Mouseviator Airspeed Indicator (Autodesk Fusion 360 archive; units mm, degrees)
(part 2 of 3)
sketch "Sketch3" plane through (0, 0, 13.75) normal (0, 0, 1) x axis (1, 0, 0)
  line L1 (0, 6.7839) -> (0, 0)
  arc A1 centre (0, 5.8437) radius 0.9477 clockwise from (-0.9442, 5.9252) to (0.9442, 5.9252)
  circle C1 centre (0, 0) radius 6
  arc A2 centre (-1.8058, 5.5576) radius 0.9477 clockwise from (-2.729, 5.3435) to (-0.933, 5.927)
  arc A3 centre (-3.4348, 4.7276) radius 0.9477 clockwise from (-4.2466, 4.2387) to (-2.7189, 5.3486)
  arc A4 centre (-4.7276, 3.4348) radius 0.9477 clockwise from (-5.3486, 2.7189) to (-4.2387, 4.2466)
  arc A5 centre (-5.5576, 1.8058) radius 0.9477 clockwise from (-5.927, 0.933) to (-5.3435, 2.729)
  arc A6 centre (-5.8437, 0) radius 0.9477 clockwise from (-5.9252, -0.9442) to (-5.9252, 0.9442)
  arc A7 centre (-5.5576, -1.8058) radius 0.9477 clockwise from (-5.3435, -2.729) to (-5.927, -0.933)
  arc A8 centre (-4.7276, -3.4348) radius 0.9477 clockwise from (-4.2387, -4.2466) to (-5.3486, -2.7189)
  arc A9 centre (-3.4348, -4.7276) radius 0.9477 clockwise from (-2.7189, -5.3486) to (-4.2466, -4.2387)
  arc A10 centre (-1.8058, -5.5576) radius 0.9477 clockwise from (-0.933, -5.927) to (-2.729, -5.3435)
  arc A11 centre (0, -5.8437) radius 0.9477 clockwise from (0.9442, -5.9252) to (-0.9442, -5.9252)
  arc A12 centre (1.8058, -5.5576) radius 0.9477 clockwise from (2.729, -5.3435) to (0.933, -5.927)
  arc A13 centre (3.4348, -4.7276) radius 0.9477 clockwise from (4.2466, -4.2387) to (2.7189, -5.3486)
  arc A14 centre (4.7276, -3.4348) radius 0.9477 clockwise from (5.3486, -2.7189) to (4.2387, -4.2466)
  arc A15 centre (5.5576, -1.8058) radius 0.9477 clockwise from (5.927, -0.933) to (5.3435, -2.729)
  arc A16 centre (5.8437, 0) radius 0.9477 clockwise from (5.9252, 0.9442) to (5.9252, -0.9442)
  arc A17 centre (5.5576, 1.8058) radius 0.9477 clockwise from (5.3435, 2.729) to (5.927, 0.933)
  arc A18 centre (4.7276, 3.4348) radius 0.9477 clockwise from (4.2387, 4.2466) to (5.3486, 2.7189)
  arc A19 centre (3.4348, 4.7276) radius 0.9477 clockwise from (2.7189, 5.3486) to (4.2466, 4.2387)
  arc A20 centre (1.8058, 5.5576) radius 0.9477 clockwise from (0.933, 5.927) to (2.729, 5.3435)
  point P3 (0.9442, 5.9252)
  point P2 (-0.9442, 5.9252)
  point P5 (0, 0)
  point P6 (0, 0)
  point P4 (0, 5.8437)
  coincident P3 C1
  coincident P2 C1
  coincident P5 P6
  vertical L1
  coincident P4 L1
  dimension "d8" C-Pattern1-Angle = 360
extrude "Extrude2" new body sketch "Sketch2" + "Sketch3" profile of S1:C1 S2:A1 S2:C1 S2:A2 S2:A3 S2:A4 S2:A5 S2:A6 S2:A7 S2:A8 S2:A9 S2:A10 S2:A11 S2:A12 S2:A13 S2:A14 S2:A15 S2:A16 S2:A17 S2:A18 S2:A19 S2:A20 S1:C2 along a picked direction blind 4
sketch "Sketch4" plane through (0, 0, 12.75) normal (0, 0, 1) x axis (-1, 0, 0)
  circle C1 centre (0, 0) radius 5
  circle C2 centre (0, 0) radius 2.15
  circle C3 centre (0.0079, 0.0724) radius 2.15
  circle C4 centre (0, 0) radius 3.75
  point P2 (0, 0)
  point P39 (0, 0)
  coincident P2 P39
  dimension "d173" diameter C1 = 10
extrude "Extrude3" add sketch "Sketch4" along a picked direction blind 0.5 named "d12_1"
loft "Loft1"
sketch "Sketch5" plane through (0, 0, 17.75) normal (0, 0, 1) x axis (-1, 0, 0)
  arc A1 centre (-1.8058, 5.5576) radius 0.9477 clockwise from (-2.7337, 5.3653) to (-0.942, 5.9475)
  arc A2 centre (-3.4348, 4.7276) radius 0.9477 clockwise from (-4.2579, 4.2579) to (-2.7337, 5.3653)
  arc A3 centre (-4.7276, 3.4348) radius 0.9477 clockwise from (-5.3653, 2.7337) to (-4.2579, 4.2579)
  arc A4 centre (-5.5576, 1.8058) radius 0.9477 clockwise from (-5.9475, 0.942) to (-5.3653, 2.7337)
  arc A5 centre (-5.8437, 0) radius 0.9477 clockwise from (-5.9475, -0.942) to (-5.9475, 0.942)
  arc A6 centre (-5.5576, -1.8058) radius 0.9477 clockwise from (-5.3653, -2.7337) to (-5.9475, -0.942)
  arc A7 centre (-4.7276, -3.4348) radius 0.9477 clockwise from (-4.2579, -4.2579) to (-5.3653, -2.7337)
  arc A8 centre (-3.4348, -4.7276) radius 0.9477 clockwise from (-2.7337, -5.3653) to (-4.2579, -4.2579)
  arc A9 centre (-1.8058, -5.5576) radius 0.9477 clockwise from (-0.942, -5.9475) to (-2.7337, -5.3653)
  arc A10 centre (0, -5.8437) radius 0.9477 clockwise from (0.942, -5.9475) to (-0.942, -5.9475)
  arc A11 centre (1.8058, -5.5576) radius 0.9477 clockwise from (2.7337, -5.3653) to (0.942, -5.9475)
  arc A12 centre (3.4348, -4.7276) radius 0.9477 clockwise from (4.2579, -4.2579) to (2.7337, -5.3653)
  arc A13 centre (4.7276, -3.4348) radius 0.9477 clockwise from (5.3653, -2.7337) to (4.2579, -4.2579)
  arc A14 centre (5.5576, -1.8058) radius 0.9477 clockwise from (5.9475, -0.942) to (5.3653, -2.7337)
  arc A15 centre (5.8437, 0) radius 0.9477 clockwise from (5.9475, 0.942) to (5.9475, -0.942)
  arc A16 centre (5.5576, 1.8058) radius 0.9477 clockwise from (5.3653, 2.7337) to (5.9475, 0.942)
  arc A17 centre (4.7276, 3.4348) radius 0.9477 clockwise from (4.2579, 4.2579) to (5.3653, 2.7337)
  arc A18 centre (3.4348, 4.7276) radius 0.9477 clockwise from (2.7337, 5.3653) to (4.2579, 4.2579)
  arc A19 centre (1.8058, 5.5576) radius 0.9477 clockwise from (0.942, 5.9475) to (2.7337, 5.3653)
  arc A20 centre (0, 5.8437) radius 0.9477 clockwise from (-0.942, 5.9475) to (0.942, 5.9475)
  circle C1 centre (0, 0) radius 6
  point P1 (0, 0)
  point P62 (0, 0)
  coincident P1 P62
  dimension "d14_1" diameter C1 = 12
sketch "Sketch6" plane through (0, 0, 0) normal (0, 1, 0) x axis (1, 0, 0)
  line L1 (0, -17.75) -> (0, -19)
  line L2 (6, -17.75) -> (0, -17.75)
  line L3 (-6, -17.75) -> (0, -17.75)
  arc A1 centre (0, -3.975) radius 15.025 clockwise from (6, -17.75) to (-6, -17.75)
  point P3 (0, -17.75)
  point P4 (0, -17.75)
  point P6 (0, -17.75)
  point P2 (0, -19)
  point P5 (6, -17.75)
  point P7 (-6, -17.75)
  vertical L1
  coincident P3 P4
  perpendicular L1 L2
  coincident P4 P6
  perpendicular L1 L3
  coincident P2 A1
  dimension "d15_1" distance P2 P3 = 1.25
  dimension "d16_1" distance P3 P5 = 6
  dimension "d18_1" distance P6 P7 = 6
revolve "Revolve2" sketch "Sketch6" AlongAngle 360 named "d19_1"
hole "Hole2" HoleDepth 3 HoleDiameter 1.75 TipAngle 180 RefDim1 3
extrude "Extrude7" add sketch "Hole for knob" to an object
decal "Decal1"
offset_faces "OffsetFaces1" distance 0.15 (= "GearGrow")
external_derived "Sketch1" bodies "Body1", "Bezel Seal"
derived_instance "DerivedInstance1"
derived_instance "DerivedInstance2"
sketch "Sketch1" plane through (0, -4.75, 0) normal (0, -1, 0) x axis (1, 0, 0)
  line L1 (0, 40.6) -> (0.6089, 39.5453)
  line L2 (-0.6089, 39.5453) -> (0, 40.6)
  circle C1 centre (-26.7653, -26.7653) radius 2.25
  circle C2 centre (-26.7653, -26.7653) radius 2
  arc A1 centre (0, 0) radius 39.55 clockwise from (0.6089, 39.5453) to (-0.6089, 39.5453)
  concentric C1 C2
  dimension "d192" diameter C1 = 4.5 (= "KnobRodThick + 0.5 mm")
extrude "Extrude3" cut sketch "Sketch1" profile of L1 C1 C2 against normal blind 13 and along normal blind 7
sketch "Sketch10" plane through (0, 2, 0) normal (0, -1, 0) x axis (1, 0, 0)
  line L1 (-41.4655, -20.5361) -> (-41.4655, 20.5361)
  line L2 (-36.4994, -34.1766) -> (-41.1157, -22.3885)
  line L3 (-23.2139, -41.1177) -> (-33.6166, -37.0564)
  line L4 (21.3665, -41.4655) -> (-21.3665, -41.4655)
  line L5 (33.6166, -37.0564) -> (23.2139, -41.1177)
  line L6 (41.1157, -22.3885) -> (36.4994, -34.1766)
  line L7 (41.4655, 20.5361) -> (41.4655, -20.5361)
  line L8 (36.4994, 34.1766) -> (41.1157, 22.3885)
  line L9 (23.2139, 41.1177) -> (33.6166, 37.0564)
  line L10 (-21.3665, 41.4655) -> (21.3665, 41.4655)
  line L11 (-33.6166, 37.0564) -> (-23.2139, 41.1177)
  line L12 (-41.1157, 22.3885) -> (-36.4994, 34.1766)
  line L13 (22.1762, -26.4285) -> (17.6767, -21.0662)
  line L14 (-17.6767, -21.0662) -> (-22.1762, -26.4285)
  line L15 (-5.1952, 24.4031) -> (-3.7897, 17.8011)
  line L16 (5.1057, 17.4692) -> (6.9993, 23.9481)
  circle C1 centre (13.5153, 6.003) radius 0.9209
  circle C2 centre (-13.4933, 6.003) radius 0.9326
  circle C3 centre (-26.7653, -26.7653) radius 2.25
  circle C4 centre (-18.76, 36.96) radius 0.9
  circle C5 centre (31.4309, -31.4309) radius 2.159
  circle C6 centre (-31.4309, 31.4309) radius 2.159
  circle C7 centre (31.4309, 31.4309) radius 2.159
  circle C8 centre (36.96, -18.76) radius 0.9
  circle C9 centre (-36.96, 18.76) radius 0.9
  circle C10 centre (-18.76, -36.96) radius 0.9
  circle C11 centre (18.76, -36.96) radius 0.9
  circle C12 centre (36.96, 18.76) radius 0.9
  circle C13 centre (-36.96, -18.76) radius 0.9
  circle C14 centre (18.76, 36.96) radius 0.9
  arc A1 centre (-36.3855, 20.5361) radius 5.08 clockwise from (-41.4655, 20.5361) to (-41.1157, 22.3885)
  arc A2 centre (-36.3855, -20.5361) radius 5.08 clockwise from (-41.1157, -22.3885) to (-41.4655, -20.5361)
  arc A3 centre (-31.7692, -32.3242) radius 5.08 clockwise from (-33.6166, -37.0564) to (-36.4994, -34.1766)
  arc A4 centre (-21.3665, -36.3855) radius 5.08 clockwise from (-21.3665, -41.4655) to (-23.2139, -41.1177)
  arc A5 centre (21.3665, -36.3855) radius 5.08 clockwise from (23.2139, -41.1177) to (21.3665, -41.4655)
  arc A6 centre (31.7692, -32.3242) radius 5.08 clockwise from (36.4994, -34.1766) to (33.6166, -37.0564)
  arc A7 centre (36.3855, -20.5361) radius 5.08 clockwise from (41.4655, -20.5361) to (41.1157, -22.3885)
  arc A8 centre (36.3855, 20.5361) radius 5.08 clockwise from (41.1157, 22.3885) to (41.4655, 20.5361)
  arc A9 centre (31.7692, 32.3242) radius 5.08 clockwise from (33.6166, 37.0564) to (36.4994, 34.1766)
  arc A10 centre (21.3665, 36.3855) radius 5.08 clockwise from (21.3665, 41.4655) to (23.2139, 41.1177)
  arc A11 centre (-21.3665, 36.3855) radius 5.08 clockwise from (-23.2139, 41.1177) to (-21.3665, 41.4655)
  arc A12 centre (-31.7692, 32.3242) radius 5.08 clockwise from (-36.4994, 34.1766) to (-33.6166, 37.0564)
  arc A13 centre (0, 0) radius 27.5 clockwise from (17.6767, -21.0662) to (-17.6767, -21.0662)
  arc A14 centre (0, 0) radius 34.5 clockwise from (22.1762, -26.4285) to (-22.1762, -26.4285)
  arc A15 centre (0, 0) radius 24.95 clockwise from (-5.1952, 24.4031) to (6.9993, 23.9481)
  arc A16 centre (0, 0) radius 18.2 clockwise from (-3.7897, 17.8011) to (5.1057, 17.4692)
  circle C15 centre (-2.3097, 10.9434) radius 1
  circle C16 centre (0, 0) radius 2.4
hole "Hole3" HoleDepth 13.5 HoleDiameter 2.5 TipAngle 180 CSDiameter 4 CSAngle 90
extrude "Extrude3" cut of existing geometry to an object offset -0.5
as_built_joint "As-built4" OffsetX 0 OffsetY 0 OffsetZ 0 AngleZ 0
position "Position7"
as_built_joint "As-built5" OffsetX 0 OffsetY 0 OffsetZ 0 AngleZ 0
motion_link "MotionLink2" Value1 30 Value2 7
as_built_joint "As-built6"
as_built_joint "As-built7" OffsetX 0 OffsetY 0 OffsetZ 0 AngleZ 0
canvas "Canvas4"
hole "Hole4" HoleDepth 10.25 HoleDiameter 2.2 TipAngle 180 CBDepth 2 CBDiameter 4.4
sketch "Sketch8" plane through (0, 0, 7.75) normal (0, 0, -1) x axis (1, 0, 0)
  line L1 (2.7496, -4.7625) -> (-2.7496, -4.7625)
  line L2 (5.4993, 0) -> (2.7496, -4.7625)
  line L3 (2.7496, 4.7625) -> (5.4993, 0)
  line L4 (-2.7496, 4.7625) -> (2.7496, 4.7625)
  line L5 (-5.4993, 0) -> (-2.7496, 4.7625)
  line L6 (-2.7496, -4.7625) -> (-5.4993, 0)
  circle C1 centre (-0.0079, 0.0724) radius 2.15
  circle C2 centre (0, 0) radius 3.75
  point P3 (0, 0)
  point P4 (0, 0)
  point P11 (0, 0)
  coincident P3 P4
  coincident P4 P11
  horizontal L1
  dimension "d261" distance P11 L6 = 4.7625 (= "3 / 16 * 1")
extrude "Extrude5" add sketch "Sketch8" along a picked direction to an object
fillet "Fillet1" radius 1.5
canvas "Canvas1"
sketch "Sketch1" plane through (0, 6.5, 0) normal (0, 1, 0) x axis (-1, 0, 0)
  line L1 (36.4994, 34.1766) -> (41.1157, 22.3885)
  line L2 (23.2139, 41.1177) -> (33.6166, 37.0564)
  line L3 (-21.3665, 41.4655) -> (21.3665, 41.4655)
  line L4 (-33.6166, 37.0564) -> (-23.2139, 41.1177)
  line L5 (-41.1157, 22.3885) -> (-36.4994, 34.1766)
  line L6 (-41.4655, -20.5361) -> (-41.4655, 20.5361)
  line L7 (-36.4994, -34.1766) -> (-41.1157, -22.3885)
  line L8 (-23.2139, -41.1177) -> (-33.6166, -37.0564)
  line L9 (21.3665, -41.4655) -> (-21.3665, -41.4655)
  line L10 (33.6166, -37.0564) -> (23.2139, -41.1177)
  line L11 (41.1157, -22.3885) -> (36.4994, -34.1766)
  line L12 (41.4655, 20.5361) -> (41.4655, -20.5361)
  curve K1 (24.8383, -25.6038) -> (25.6038, -24.8383)
  curve K2 (25.6038, -24.8383) -> (28.6503, -25.5367)
  curve K3 (28.6503, -25.5367) -> (28.8285, -25.8677)
  curve K4 (28.9576, -26.2589) -> (28.9895, -27.1055)
  curve K5 (27.1055, -28.9895) -> (26.2589, -28.9576)
  curve K6 (25.8677, -28.8285) -> (25.5367, -28.6503)
  curve K7 (25.5367, -28.6503) -> (24.8383, -25.6038)
  line L13 (41.1157, 22.3885) -> (36.4994, 34.1766)
  line L14 (41.4655, -20.5361) -> (41.4655, 20.5361)
  line L15 (36.4994, -34.1766) -> (41.1157, -22.3885)
  line L16 (23.2139, -41.1177) -> (33.6166, -37.0564)
  line L17 (-21.3665, -41.4655) -> (21.3665, -41.4655)
  line L18 (-33.6166, -37.0564) -> (-23.2139, -41.1177)
  line L19 (-41.1157, -22.3885) -> (-36.4994, -34.1766)
  line L20 (-41.4655, 20.5361) -> (-41.4655, -20.5361)
  line L21 (-36.4994, 34.1766) -> (-41.1157, 22.3885)
  line L22 (-23.2139, 41.1177) -> (-33.6166, 37.0564)
  line L23 (21.3665, 41.4655) -> (-21.3665, 41.4655)
  line L24 (33.6166, 37.0564) -> (23.2139, 41.1177)
  arc A1 centre (0, 0) radius 35 clockwise from (17.484, -30.3201) to (30.3201, -17.484)
  arc A2 centre (36.3855, 20.5361) radius 5.08 clockwise from (41.1157, 22.3885) to (41.4655, 20.5361)
  arc A3 centre (31.7692, 32.3242) radius 5.08 clockwise from (33.6166, 37.0564) to (36.4994, 34.1766)
  arc A4 centre (21.3665, 36.3855) radius 5.08 clockwise from (21.3665, 41.4655) to (23.2139, 41.1177)
  arc A5 centre (-21.3665, 36.3855) radius 5.08 clockwise from (-23.2139, 41.1177) to (-21.3665, 41.4655)
  arc A6 centre (-31.7692, 32.3242) radius 5.08 clockwise from (-36.4994, 34.1766) to (-33.6166, 37.0564)
  arc A7 centre (-36.3855, 20.5361) radius 5.08 clockwise from (-41.4655, 20.5361) to (-41.1157, 22.3885)
  arc A8 centre (-36.3855, -20.5361) radius 5.08 clockwise from (-41.1157, -22.3885) to (-41.4655, -20.5361)
  arc A9 centre (-31.7692, -32.3242) radius 5.08 clockwise from (-33.6166, -37.0564) to (-36.4994, -34.1766)
  arc A10 centre (-21.3665, -36.3855) radius 5.08 clockwise from (-21.3665, -41.4655) to (-23.2139, -41.1177)
  arc A11 centre (21.3665, -36.3855) radius 5.08 clockwise from (23.2139, -41.1177) to (21.3665, -41.4655)
  arc A12 centre (31.7692, -32.3242) radius 5.08 clockwise from (36.4994, -34.1766) to (33.6166, -37.0564)
  arc A13 centre (36.3855, -20.5361) radius 5.08 clockwise from (41.4655, -20.5361) to (41.1157, -22.3885)
  circle C1 centre (-36.96, -18.76) radius 0.9
  circle C2 centre (36.96, -18.76) radius 0.9
  circle C3 centre (-18.76, 36.96) radius 0.9
  circle C4 centre (31.4309, 31.4309) radius 2.159
  circle C5 centre (18.76, -36.96) radius 0.9
  circle C6 centre (-31.4309, 31.4309) radius 2.159
  circle C7 centre (36.96, 18.76) radius 0.9
  circle C8 centre (18.76, 36.96) radius 0.9
  circle C9 centre (-18.76, -36.96) radius 0.9
  circle C10 centre (-36.96, 18.76) radius 0.9
  circle C11 centre (-31.4309, -31.4309) radius 2.159
  circle C12 centre (0, 0) radius 30
  arc A14 centre (26.7653, -26.7653) radius 2.25 clockwise from (28.8285, -25.8677) to (28.9576, -26.2589)
  arc A15 centre (26.7653, -26.7653) radius 2.25 clockwise from (28.9895, -27.1055) to (27.1055, -28.9895)
  arc A16 centre (26.7653, -26.7653) radius 2.25 clockwise from (26.2589, -28.9576) to (25.8677, -28.8285)
  circle C13 centre (-31.4309, -31.4309) radius 2.159
  circle C14 centre (31.4309, 31.4309) radius 2.159
  circle C15 centre (-31.4309, 31.4309) radius 2.159
  circle C16 centre (0, 0) radius 35.5256
  circle C17 centre (-36.96, 18.76) radius 0.9
  circle C18 centre (-18.76, -36.96) radius 0.9
  circle C19 centre (36.96, -18.76) radius 0.9
  circle C20 centre (18.76, 36.96) radius 0.9
  circle C21 centre (36.96, 18.76) radius 0.9
  circle C22 centre (18.76, -36.96) radius 0.9
  circle C23 centre (-36.96, -18.76) radius 0.9
  circle C24 centre (-18.76, 36.96) radius 0.9
  arc A17 centre (36.3855, 20.5361) radius 5.08 clockwise from (41.1157, 22.3885) to (41.4655, 20.5361)
  arc A18 centre (36.3855, -20.5361) radius 5.08 clockwise from (41.4655, -20.5361) to (41.1157, -22.3885)
  arc A19 centre (31.7692, -32.3242) radius 5.08 clockwise from (36.4994, -34.1766) to (33.6166, -37.0564)
  arc A20 centre (21.3665, -36.3855) radius 5.08 clockwise from (23.2139, -41.1177) to (21.3665, -41.4655)
  arc A21 centre (-21.3665, -36.3855) radius 5.08 clockwise from (-21.3665, -41.4655) to (-23.2139, -41.1177)
  arc A22 centre (-31.7692, -32.3242) radius 5.08 clockwise from (-33.6166, -37.0564) to (-36.4994, -34.1766)
  arc A23 centre (-36.3855, -20.5361) radius 5.08 clockwise from (-41.1157, -22.3885) to (-41.4655, -20.5361)
  arc A24 centre (-36.3855, 20.5361) radius 5.08 clockwise from (-41.4655, 20.5361) to (-41.1157, 22.3885)
  arc A25 centre (-31.7692, 32.3242) radius 5.08 clockwise from (-36.4994, 34.1766) to (-33.6166, 37.0564)
  arc A26 centre (-21.3665, 36.3855) radius 5.08 clockwise from (-23.2139, 41.1177) to (-21.3665, 41.4655)
  arc A27 centre (21.3665, 36.3855) radius 5.08 clockwise from (21.3665, 41.4655) to (23.2139, 41.1177)
  arc A28 centre (31.7692, 32.3242) radius 5.08 clockwise from (33.6166, 37.0564) to (36.4994, 34.1766)
  dimension "d267" diameter C12 = 60
extrude "Extrude1" new body sketch "Sketch1" profile of A2 L1 A3 L2 A4 L3 A5 L4 A6 L5 A7 L6 A8 L7 A9 L8 A10 L9 A11 L10 A12 L11 A13 L12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 along normal blind 2
sketch "Sketch2" plane through (0, 8.5, 0) normal (0, 1, 0) x axis (-1, 0, 0)
  line L1 (36.4994, 34.1766) -> (41.1157, 22.3885)
  line L2 (23.2139, 41.1177) -> (33.6166, 37.0564)
  line L3 (-21.3665, 41.4655) -> (21.3665, 41.4655)
  line L4 (-33.6166, 37.0564) -> (-23.2139, 41.1177)
  line L5 (-41.1157, 22.3885) -> (-36.4994, 34.1766)
  line L6 (-41.4655, -20.5361) -> (-41.4655, 20.5361)
  line L7 (-36.4994, -34.1766) -> (-41.1157, -22.3885)
  line L8 (-23.2139, -41.1177) -> (-33.6166, -37.0564)
  line L9 (21.3665, -41.4655) -> (-21.3665, -41.4655)
  line L10 (33.6166, -37.0564) -> (23.2139, -41.1177)
  line L11 (41.1157, -22.3885) -> (36.4994, -34.1766)
  line L12 (41.4655, 20.5361) -> (41.4655, -20.5361)
  circle C1 centre (18.76, 36.96) radius 0.9
  circle C2 centre (31.4309, 31.4309) radius 2.159
  circle C3 centre (-18.76, -36.96) radius 0.9
  circle C4 centre (-36.96, 18.76) radius 0.9
  circle C5 centre (-31.4309, -31.4309) radius 2.159
  circle C6 centre (-18.76, 36.96) radius 0.9
  circle C7 centre (36.96, -18.76) radius 0.9
  circle C8 centre (36.96, 18.76) radius 0.9
  circle C9 centre (18.76, -36.96) radius 0.9
  circle C10 centre (-36.96, -18.76) radius 0.9
  circle C11 centre (-31.4309, 31.4309) radius 2.159
  arc A1 centre (36.3855, 20.5361) radius 5.08 clockwise from (41.1157, 22.3885) to (41.4655, 20.5361)
  arc A2 centre (31.7692, 32.3242) radius 5.08 clockwise from (33.6166, 37.0564) to (36.4994, 34.1766)
  arc A3 centre (21.3665, 36.3855) radius 5.08 clockwise from (21.3665, 41.4655) to (23.2139, 41.1177)
  arc A4 centre (-21.3665, 36.3855) radius 5.08 clockwise from (-23.2139, 41.1177) to (-21.3665, 41.4655)
  arc A5 centre (-31.7692, 32.3242) radius 5.08 clockwise from (-36.4994, 34.1766) to (-33.6166, 37.0564)
  arc A6 centre (-36.3855, 20.5361) radius 5.08 clockwise from (-41.4655, 20.5361) to (-41.1157, 22.3885)
  arc A7 centre (-36.3855, -20.5361) radius 5.08 clockwise from (-41.1157, -22.3885) to (-41.4655, -20.5361)
  arc A8 centre (-31.7692, -32.3242) radius 5.08 clockwise from (-33.6166, -37.0564) to (-36.4994, -34.1766)
  arc A9 centre (-21.3665, -36.3855) radius 5.08 clockwise from (-21.3665, -41.4655) to (-23.2139, -41.1177)
  arc A10 centre (21.3665, -36.3855) radius 5.08 clockwise from (23.2139, -41.1177) to (21.3665, -41.4655)
  arc A11 centre (31.7692, -32.3242) radius 5.08 clockwise from (36.4994, -34.1766) to (33.6166, -37.0564)
  arc A12 centre (36.3855, -20.5361) radius 5.08 clockwise from (41.4655, -20.5361) to (41.1157, -22.3885)
  circle C12 centre (0, 0) radius 38.075
  circle C13 centre (0, 0) radius 36.575
  point P1 (0, 0)
  point P49 (0, 0)
  point P50 (0, 0)
  coincident P1 P49
  coincident P1 P50
  dimension "d270" diameter C12 = 76.15
  dimension "d273" distance C12 C13 = 1.5
work_plane "WorkPlane1" AlongDistance 45
sketch "Sketch3" plane through (0, 53.5, 0) normal (0, 1, 0) x axis (1, 0, 0)
  circle C1 centre (0, 0) radius 32.7575
  circle C2 centre (0, 0) radius 29.7575
  point P1 (0, 0)
  point P2 (0, 0)
  coincident P1 P2
  concentric C1 C2
  dimension "d275" distance C1 C2 = 3
extrude "Extrude3" add sketch "Sketch2" profile of C12 C13 along normal blind 45
sketch "Sketch4" plane through (0, 53.5, 0) normal (0, 1, 0) x axis (-1, 0, 0)
  line L1 (-2, -44.6407) -> (-2, 0)
  line L2 (2, 0) -> (2, -44.6407)
  line L3 (0, -44.6407) -> (0, 0)
  circle C1 centre (0, 0) radius 36.575
  circle C2 centre (0, 0) radius 38.075
  arc A1 centre (0, -44.6407) radius 2 clockwise from (2, -44.6407) to (-2, -44.6407)
  arc A2 centre (0, 0) radius 2 clockwise from (-2, 0) to (2, 0)
  point P2 (0, 0)
  point P7 (0, 0)
  tangent L1 A1
  tangent A1 L2
  parallel L1 L2
  tangent L2 A2
  tangent L1 A2
  vertical L3
  coincident P2 P7
  dimension "d280" diameter A1 = 4
extrude "Extrude4" add sketch "Sketch4" profile of C1 C2 L1 L2 A2 along normal blind 2
extrude "Extrude5" cut sketch "Sketch4" profile of C1 C2 L1 A1 L2 A2 to an object Side2Offset 0
canvas "Canvas2"
fillet "Fillet1" radius 2.5
hole "Hole1" HoleDepth 10.25 HoleDiameter 8.526 TipAngle 180
sketch "Sketch1" plane through (0, 55.5, 0) normal (0, 1, 0) x axis (-1, 0, 0)
  curve K1 (2, -4.2954) -> (4.9244, -1.3229)
  line L1 (2, -35.5187) -> (2, -4.2954)
  line L2 (-2, -3.8753) -> (-2, -35.5187)
  curve K2 (-2.7898, -3.2234) -> (-2, -3.8753)
  curve K3 (4.9244, 1.3229) -> (-2.7898, 3.2234)
  arc A1 centre (0, 0) radius 35.575 clockwise from (-2, -35.5187) to (2, -35.5187)
  arc A2 centre (0, 0) radius 4.263 clockwise from (-2.7898, -3.2234) to (-2.7898, 3.2234)
  arc A3 centre (0, 0) radius 5.099 clockwise from (4.9244, 1.3229) to (4.9244, -1.3229)
  circle C1 centre (0, 0) radius 6.542
  circle C2 centre (0, 0) radius 2.5
  concentric A1 C1
  concentric A2 C2
  dimension "d290" diameter C2 = 5
extrude "Extrude1" new body sketch "Sketch1" profile of K1 L1 L2 K2 A2 K3 A3 C1 C2 to an object offset 1.5
thread "Thread1" ThreadOffset 0 ThreadLength 10
sketch "Sketch2" plane through (0, 55.5, 0) normal (0, 1, 0) x axis (-1, 0, 0)
  curve K1 (-2.1684, -4.422) -> (-2.3623, 3.3149)
  curve K2 (2.3623, 3.3149) -> (2.1684, -4.422)
  arc A1 centre (0, 0) radius 4.925 clockwise from (2.1684, -4.422) to (-2.1684, -4.422)
  arc A2 centre (0, 0) radius 4.0705 clockwise from (-2.3623, 3.3149) to (2.3623, 3.3149)
  circle C1 centre (0, 0) radius 2.5
  circle C2 centre (0, 0) radius 6
  concentric A1 C2
  dimension "d296" diameter C2 = 12
extrude "Extrude2" add sketch "Sketch2" along normal blind 5
mirror "Mirror1" mirrorStitchTolerance 0.1
extrude "Extrude3" cut sketch "Sketch4" profile of C1 L1 L2 A2 to an object Side2Offset 0
position "Position9"
remove_instance "RemoveInstance12"
sketch "Sketch1" plane through (0, -8.25, 0) normal (0, -1, 0) x axis (1, 0, 0)
  line L1 (-40.1846, 22.0238) -> (-35.5682, 33.812)
  line L2 (-40.4655, -20.5361) -> (-40.4655, 20.5361)
  line L3 (-35.5682, -33.812) -> (-40.1846, -22.0238)
  line L4 (-22.8502, -40.1861) -> (-33.2529, -36.1249)
  line L5 (21.3665, -40.4655) -> (-21.3665, -40.4655)
  line L6 (33.2529, -36.1249) -> (22.8502, -40.1861)
  line L7 (40.1846, -22.0238) -> (35.5682, -33.812)
  line L8 (40.4655, 20.5361) -> (40.4655, -20.5361)
  line L9 (35.5682, 33.812) -> (40.1846, 22.0238)
  line L10 (22.8502, 40.1861) -> (33.2529, 36.1249)
  line L11 (-21.3665, 40.4655) -> (21.3665, 40.4655)
  line L12 (-33.2529, 36.1249) -> (-22.8502, 40.1861)
  line L13 (-26.1337, -30.6238) -> (-29.1858, -33.676)
  line L14 (-33.676, -29.1858) -> (-30.6238, -26.1337)
  line L15 (-30.6238, -26.1337) -> (-26.1337, -30.6238)
  line L16 (-29.1858, -33.676) -> (-33.676, -29.1858)
  line L17 (-50, -50) -> (50, -50)
  line L18 (-50, 50) -> (-50, -50)
  line L19 (50, 50) -> (-50, 50)
  line L20 (50, -50) -> (50, 50)
  line L21 (-50, 50) -> (50, -50)
  line L22 (50, 50) -> (-50, -50)
  arc A1 centre (-36.3855, 20.5361) radius 4.08 clockwise from (-40.4655, 20.5361) to (-40.1846, 22.0238)
  arc A2 centre (-36.3855, -20.5361) radius 4.08 clockwise from (-40.1846, -22.0238) to (-40.4655, -20.5361)
  arc A3 centre (-31.7692, -32.3242) radius 4.08 clockwise from (-33.2529, -36.1249) to (-35.5682, -33.812)
  arc A4 centre (-21.3665, -36.3855) radius 4.08 clockwise from (-21.3665, -40.4655) to (-22.8502, -40.1861)
  arc A5 centre (21.3665, -36.3855) radius 4.08 clockwise from (22.8502, -40.1861) to (21.3665, -40.4655)
  arc A6 centre (31.7692, -32.3242) radius 4.08 clockwise from (35.5682, -33.812) to (33.2529, -36.1249)
  arc A7 centre (36.3855, -20.5361) radius 4.08 clockwise from (40.4655, -20.5361) to (40.1846, -22.0238)
  arc A8 centre (36.3855, 20.5361) radius 4.08 clockwise from (40.1846, 22.0238) to (40.4655, 20.5361)
  arc A9 centre (31.7692, 32.3242) radius 4.08 clockwise from (33.2529, 36.1249) to (35.5682, 33.812)
  arc A10 centre (21.3665, 36.3855) radius 4.08 clockwise from (21.3665, 40.4655) to (22.8502, 40.1861)
  arc A11 centre (-21.3665, 36.3855) radius 4.08 clockwise from (-22.8502, 40.1861) to (-21.3665, 40.4655)
  arc A12 centre (-31.7692, 32.3242) radius 4.08 clockwise from (-35.5682, 33.812) to (-33.2529, 36.1249)
  arc A13 centre (-26.7653, -26.7653) radius 2.25 clockwise from (-27.1055, -28.9895) to (-28.9895, -27.1055)
  arc A14 centre (0, 0) radius 39.6875 clockwise from (-28.9895, -27.1055) to (-27.1055, -28.9895)
  circle C1 centre (31.4309, -31.4309) radius 2.159
  circle C2 centre (-31.4309, 31.4309) radius 2.159
  circle C3 centre (31.4309, 31.4309) radius 2.159
  circle C4 centre (18.76, 36.96) radius 1.75
  circle C5 centre (36.96, -18.76) radius 1.75
  circle C6 centre (-18.76, -36.96) radius 1.75
  circle C7 centre (-36.96, 18.76) radius 1.75
  circle C8 centre (-18.76, 36.96) radius 1.75
  circle C9 centre (-36.96, -18.76) radius 1.75
  circle C10 centre (18.76, -36.96) radius 1.75
  circle C11 centre (36.96, 18.76) radius 1.75
  circle C12 centre (31.4309, 31.4309) radius 2.159
  circle C13 centre (-31.4309, -31.4309) radius 3.175
  circle C14 centre (31.4309, -31.4309) radius 2.159
  circle C15 centre (-31.4309, -31.4309) radius 2.159
  circle C16 centre (0, 0) radius 40.259
  circle C17 centre (-31.4309, 31.4309) radius 2.159
  point P55 (0, 0)
  point P56 (0, 0)
  point P64 (-29.1858, -33.676)
  point P60 (-33.676, -29.1858)
  point P63 (-31.4309, -31.4309)
  point P59 (-30.6238, -26.1337)
  point P62 (-26.1337, -30.6238)
  point P57 (-31.4309, -31.4309)
  point P70 (0, 0)
  point P68 (-50, 50)
  point P69 (50, 50)
  point P67 (-50, -50)
  equal C15 C17
  equal C14 C15
  equal C12 C14
  coincident P55 P56
  concentric C13 C15
  perpendicular L13 L16
  parallel L15 L16
  parallel L13 L14
  coincident P64 C13
  coincident P60 C13
  midpoint P63 L16
  coincident P59 C16
  coincident P62 C16
  coincident P57 P63
  horizontal L17
  perpendicular L17 L18
  parallel L17 L19
  parallel L18 L20
  coincident L21 P70
  coincident L22 P70
  coincident P56 P70
  dimension "d305" = 0 (= "Instrumentknobdimension")
  dimension "d306" distance P68 P69 = 100
  dimension "d307" distance P67 P68 = 100
extrude "Extrude1" new body sketch "Sketch1" profile of L1 A1 L2 A2 L3 A3 L4 A4 L5 A5 L6 A6 L7 A7 L8 A8 L9 A9 L10 A10 L11 A11 L12 A12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 along normal blind 3
sketch "Sketch2" plane through (0, -11.25, 0) normal (0, -1, 0) x axis (1, 0, 0)
  line L1 (-50, 50) -> (50, 50)
  line L2 (-50, -50) -> (-50, 50)
  line L3 (50, -50) -> (-50, -50)
  line L4 (50, 50) -> (50, -50)
  circle C1 centre (-31.4309, 31.4309) radius 2.159
  circle C2 centre (31.4309, 31.4309) radius 2.159
  arc A1 centre (0, 0) radius 39.6875 clockwise from (-28.9895, -27.1055) to (-27.1055, -28.9895)
  arc A2 centre (-26.7653, -26.7653) radius 2.25 clockwise from (-27.1055, -28.9895) to (-28.9895, -27.1055)
  circle C3 centre (31.4309, -31.4309) radius 2.159
sketch "Glass Export" plane through (0, -4.75, 0) normal (0, -1, 0) x axis (1, 0, 0)
  line L1 (0, 40.6) -> (0.6089, 39.5453)
  line L2 (-0.6089, 39.5453) -> (0, 40.6)
  line L3 (0, 40.6) -> (-0.6089, 39.5453)
  line L4 (0.6089, 39.5453) -> (0, 40.6)
  arc A1 centre (-26.7653, -26.7653) radius 2.25 clockwise from (-29.0125, -26.879) to (-26.879, -29.0125)
  arc A2 centre (0, 0) radius 39.55 clockwise from (0.6089, 39.5453) to (-26.879, -29.0125)
  arc A3 centre (0, 0) radius 39.55 clockwise from (-29.0125, -26.879) to (-0.6089, 39.5453)
  arc A4 centre (-26.7653, -26.7653) radius 2.25 clockwise from (-29.0125, -26.879) to (-26.879, -29.0125)
  arc A5 centre (0, 0) radius 39.55 clockwise from (0.6089, 39.5453) to (-26.879, -29.0125)
  arc A6 centre (0, 0) radius 39.55 clockwise from (-29.0125, -26.879) to (-0.6089, 39.5453)
offset_faces "OffsetFaces1" distance 3
offset_faces "OffsetFaces1" distance 3
offset_faces "OffsetFaces2" distance 3
move_face "MoveFace1"
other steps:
derived_base_feature "Sketch1" bodies "Bezel Seal"
extrude "Extrude1" cut sketch "Sketch1" profile of L1 C1 C2 against normal blind 13 and along normal blind 7
derived_base_feature "Sketch1" bodies "Body1"
extrude "Extrude1" cut sketch "Sketch1" profile of L1 C1 C2 against normal blind 13 and along normal blind 7
derived_base_feature "Derived Base Feature" bodies "Standard Bezel", "Airspeed Bezel"
thread "Thread1" ThreadOffset 0 ThreadDepth 10
hole "Hole2" HoleDepth 3 HoleDiameter 1.75 TipAngle 180 RefDim1 3
extrude "Extrude9" cut sketch "Sketch1" profile of L1 C1 C2 against normal blind 13 and along normal blind 7
create_component "CreateComponent2"
create_component "CreateComponent3"
joint_origin "JointOrigin2"
joint_origin "JointOrigin3"
create_component "CreateComponent4"
joint_origin "JointOrigin2"
joint_origin "JointOrigin4"
create_component "CreateComponent5"
create_component "CreateComponent6"
remove_instance "RemoveInstance3"
remove_instance "RemoveInstance4"
create_component "CreateComponent8"
create_component "CreateComponent9"
extrude "Extrude1" cut sketch "Hole for knob" profile of C1 to an object
create_component "CreateComponent10"
create_component "CreateComponent12"
joint_origin "JointOrigin8"
joint_origin "JointOrigin4"
create_component "CreateComponent1"
create_component "CreateComponent2"
extrude "Extrude3" cut sketch "Sketch1" profile of L1 C1 C2 against normal blind 13 and along normal blind 7
create_component "CreateComponent14"
remove_instance "RemoveInstance9"
joint_origin "JointOrigin1"
joint_origin "JointOrigin1"
create_component "CreateComponent15"
create_component "CreateComponent1"
create_component "CreateComponent16"
named bodies: "Knob", "Body1", "Bezel Seal", "Standard Bezel", "Airspeed Bezel"

design "X27.168 Stepper"
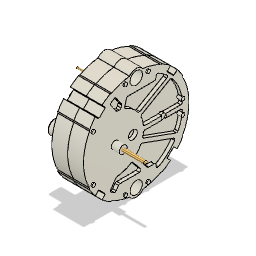
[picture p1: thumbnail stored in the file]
canvas "Canvas1"
sketch "Sketch1" plane through (0, 0, 0) normal (1, 0, 0) x axis (0, 0, -1)
  line L1 (-4.4067, 18.5277) -> (-4.4067, -0.8601)
  line L2 (-4.4067, -19.8773) -> (-4.4067, -0.8601)
  line L3 (21.636, -0.8601) -> (-4.4067, -0.8601)
  line L4 (-24.4318, -0.8601) -> (-4.4067, -0.8601)
  line L5 (2.9837, 12.4223) -> (2.5631, 12.4223)
  line L6 (8.873, 6.1148) -> (8.873, 6.5351)
  line L7 (8.873, -8.2553) -> (8.873, -7.835)
  line L8 (2.5727, -14.1374) -> (2.9927, -14.1374)
  line L9 (-11.8062, -14.1374) -> (-11.3861, -14.1374)
  line L10 (-17.6759, -8.2743) -> (-17.6759, -7.8551)
  line L11 (-17.6759, 6.1349) -> (-17.6759, 6.5541)
  line L12 (-11.3861, 12.4172) -> (-11.8062, 12.4172)
  line L13 (-1.9645, -0.3096) -> (2.8964, -0.3096)
  line L14 (5.233, 7.5224) -> (-2.8122, 2.8822)
  line L15 (8.2503, -0.2975) -> (3.9018, -0.2975)
  line L16 (8.6743, 0.6405) -> (8.6971, 0.1445)
  line L17 (-1.9603, -1.4205) -> (2.9074, -1.4205)
  line L18 (6.9763, -6.5951) -> (-2.2776, -3.228)
  line L19 (6.2953, -7.5343) -> (-2.657, -4.2788)
  line L20 (-1.2541, -10.8992) -> (-4.5555, -6.9779)
  line L21 (0.6697, -11.0649) -> (-0.9101, -11.0649)
  line L22 (8.2552, -1.417) -> (3.9081, -1.417)
  line L23 (8.671, -2.3738) -> (8.6952, -1.8597)
  line L24 (-15.1488, 7.9637) -> (-16.0708, 8.8862)
  line L25 (-13.2614, 9.6883) -> (-14.9498, 8.0007)
  line L26 (-14.1646, 10.7942) -> (-13.274, 9.873)
  line L27 (0.6688, 9.3329) -> (-6.7552, 9.3329)
  line L28 (4.2578, 8.2578) -> (-3.3795, 3.8493)
  line L29 (-7.6798, 7.1524) -> (-7.1916, 9.0071)
  arc A1 centre (-4.4067, 12.6425) radius 2.35 clockwise from (-6.3118, 14.0184) to (-2.5017, 14.0184)
  arc A2 centre (-4.4067, -14.3661) radius 2.35 clockwise from (-2.4989, -15.7383) to (-6.3145, -15.7383)
  arc A3 centre (-4.4067, -0.8601) radius 15 clockwise from (-11.3861, 12.4172) to (-6.3118, 14.0184)
  arc A4 centre (-4.4067, -0.8601) radius 15 clockwise from (-17.6759, -7.8551) to (-17.6759, 6.1349)
  arc A5 centre (-4.4067, -0.8601) radius 15 clockwise from (-6.3145, -15.7383) to (-11.3861, -14.1374)
  arc A6 centre (-4.4067, -0.8601) radius 15 clockwise from (2.5727, -14.1374) to (-2.4989, -15.7383)
  arc A7 centre (-4.4067, -0.8601) radius 15 clockwise from (8.873, 6.1148) to (8.873, -7.835)
  arc A8 centre (-4.4067, -0.8601) radius 15 clockwise from (-2.5017, 14.0184) to (2.5631, 12.4223)
  circle C1 centre (-4.4067, 12.6425) radius 0.9209
  circle C2 centre (-4.4067, 12.6425) radius 1.2263
  circle C3 centre (-4.4067, 12.6425) radius 1.5619
  circle C4 centre (-4.4067, 12.6425) radius 1.7817
  circle C5 centre (-10.4097, -0.8601) radius 1
  circle C6 centre (-10.4097, -0.8601) radius 1.1043
  circle C7 centre (-10.4097, -0.8601) radius 0.9029
  circle C8 centre (-10.4097, -0.8601) radius 0.5
  circle C9 centre (-4.4067, -14.3661) radius 1.75
  circle C10 centre (-4.4067, -14.3661) radius 1.5597
  circle C11 centre (-4.4067, -14.3661) radius 1.2196
  circle C12 centre (-4.4067, -14.3661) radius 0.9326
  circle C13 centre (-7.6531, -14.4857) radius 0.5
  circle C14 centre (-1.16, -14.4857) radius 0.5
  circle C15 centre (-1.1623, 12.7607) radius 0.5
  circle C16 centre (-7.6764, 12.7607) radius 0.5
  circle C17 centre (8.641, 1.1394) radius 0.5
  circle C18 centre (8.6402, -2.8729) radius 0.5
  circle C19 centre (-16.7858, -7.4196) radius 0.5
  circle C20 centre (-16.789, 5.6908) radius 0.5
  circle C21 centre (-5.3601, -0.8601) radius 1.25
  circle C22 centre (3.4058, -0.8601) radius 0.75
  arc A9 centre (8.2742, 0.1251) radius 0.4233 clockwise from (8.6971, 0.1445) to (8.2503, -0.2975)
  arc A10 centre (-1.9645, 0.1348) radius 0.4445 clockwise from (-1.9645, -0.3096) to (-2.4073, 0.0969)
  arc A11 centre (-8.9083, -0.46) radius 6.5247 clockwise from (-3.0084, 2.3264) to (-2.4073, 0.0969)
  arc A12 centre (-2.5858, 2.4897) radius 0.4531 clockwise from (-3.0084, 2.3264) to (-2.8122, 2.8822)
  arc A13 centre (5.4542, 7.1389) radius 0.4428 clockwise from (5.233, 7.5224) to (5.7979, 7.4181)
  arc A14 centre (-4.6199, -1.0441) radius 13.4216 clockwise from (5.7979, 7.4181) to (8.5331, 1.6276)
  arc A15 centre (-1.9603, -1.8673) radius 0.4467 clockwise from (-2.4022, -1.8018) to (-1.9603, -1.4205)
  arc A16 centre (-5.829, -1.6642) radius 3.4295 clockwise from (-2.4022, -1.8018) to (-2.5612, -2.705)
  arc A17 centre (-2.1681, -2.8302) radius 0.4125 clockwise from (-2.2776, -3.228) to (-2.5612, -2.705)
  arc A18 centre (7.1248, -6.1871) radius 0.4341 clockwise from (7.5084, -6.3904) to (6.9763, -6.5951)
  arc A19 centre (-1.0924, -1.8332) radius 9.7335 clockwise from (8.5209, -3.3585) to (7.5084, -6.3904)
  arc A20 centre (-2.8111, -4.7025) radius 0.4508 clockwise from (-3.2095, -4.4917) to (-2.657, -4.2788)
  arc A21 centre (-11.5739, -0.0679) radius 9.4621 clockwise from (-3.2095, -4.4917) to (-4.5302, -6.3861)
  arc A22 centre (-4.2204, -6.6958) radius 0.438 clockwise from (-4.5555, -6.9779) to (-4.5302, -6.3861)
  arc A23 centre (-0.9101, -10.6248) radius 0.44 clockwise from (-0.9101, -11.0649) to (-1.2541, -10.8992)
  arc A24 centre (0.6697, -11.6246) radius 0.5597 clockwise from (0.6697, -11.0649) to (1.2294, -11.6221)
  arc A25 centre (10.2849, -11.5808) radius 9.0556 clockwise from (1.24, -12.0198) to (1.2294, -11.6221)
  arc A26 centre (1.6687, -12.0367) radius 0.429 clockwise from (1.888, -12.4055) to (1.24, -12.0198)
  arc A27 centre (-4.3755, -0.8963) radius 13.1031 clockwise from (6.5021, -8.2019) to (1.888, -12.4055)
  arc A28 centre (6.1453, -7.9466) radius 0.4387 clockwise from (6.2953, -7.5343) to (6.5021, -8.2019)
  arc A29 centre (8.2552, -1.857) radius 0.44 clockwise from (8.2552, -1.417) to (8.6952, -1.8597)
  arc A30 centre (-10.4198, -0.7543) radius 8.1695 clockwise from (-5.9889, -7.6178) to (-9.8026, -8.9004)
  arc A31 centre (-5.742, -8.0002) radius 0.4552 clockwise from (-5.9889, -7.6178) to (-5.4059, -7.6932)
  arc A32 centre (-34.8025, -34.5427) radius 39.8127 clockwise from (-5.4059, -7.6932) to (-3.1904, -10.3408)
  arc A33 centre (-3.5126, -10.633) radius 0.435 clockwise from (-3.1904, -10.3408) to (-3.5059, -11.0679)
  arc A34 centre (-6.2324, 166.0207) radius 177.1096 clockwise from (-3.5059, -11.0679) to (-8.9589, -11.0679)
  arc A35 centre (-8.9682, -11.6735) radius 0.6057 clockwise from (-9.4459, -11.3011) to (-8.9589, -11.0679)
  arc A36 centre (1.2154, -19.6129) radius 13.5185 clockwise from (-10.1249, -12.2545) to (-9.4459, -11.3011)
  arc A37 centre (-10.5017, -12.01) radius 0.4492 clockwise from (-10.1249, -12.2545) to (-10.7148, -12.4054)
  arc A38 centre (-5.2803, -2.3221) radius 11.4546 clockwise from (-10.7148, -12.4054) to (-11.5242, -11.9253)
  arc A39 centre (-11.2794, -11.5306) radius 0.4644 clockwise from (-11.5242, -11.9253) to (-11.6751, -11.2874)
  arc A40 centre (6.3834, -22.3862) radius 21.1965 clockwise from (-11.6751, -11.2874) to (-10.1318, -9.0993)
  arc A41 centre (-9.7703, -9.3257) radius 0.4265 clockwise from (-10.1318, -9.0993) to (-9.8026, -8.9004)
  arc A42 centre (-13.3772, 9.7732) radius 0.1436 clockwise from (-13.274, 9.873) to (-13.2614, 9.6883)
  arc A43 centre (-15.0762, 8.1271) radius 0.1788 clockwise from (-14.9498, 8.0007) to (-15.1488, 7.9637)
  arc A44 centre (-4.4067, -0.8601) radius 15.2 clockwise from (-14.1646, 10.7942) to (-11.8062, 12.4172)
  arc A45 centre (-4.4067, -0.8601) radius 15.2 clockwise from (-17.6759, 6.5541) to (-16.0708, 8.8862)
  arc A46 centre (27.3451, -12.2651) radius 31.885 clockwise from (4.4145, 9.8899) to (5.3368, 10.8063)
  arc A47 centre (4.4478, 9.7984) radius 0.0973 clockwise from (4.4326, 9.7023) to (4.4145, 9.8899)
  arc A48 centre (-158.4507, -154.9056) radius 231.5744 clockwise from (4.4326, 9.7023) to (6.1572, 7.9777)
  arc A49 centre (6.2246, 8.0786) radius 0.1214 clockwise from (6.3071, 7.9895) to (6.1572, 7.9777)
  arc A50 centre (-0.3735, 15.8934) radius 10.349 clockwise from (7.2502, 8.8947) to (6.3071, 7.9895)
  arc A51 centre (-4.4067, -0.8601) radius 15.2 clockwise from (7.2502, 8.8947) to (8.873, 6.5351)
  arc A52 centre (-4.4067, -0.8601) radius 15.2 clockwise from (2.9837, 12.4223) to (5.3368, 10.8063)
  arc A53 centre (93.0217, 77.7849) radius 125.8718 clockwise from (5.3401, -12.5237) to (4.4051, -11.6064)
  arc A54 centre (4.5901, -11.5514) radius 0.193 clockwise from (4.4051, -11.6064) to (4.4513, -11.4172)
  arc A55 centre (37.8756, -43.7201) radius 46.4828 clockwise from (4.4513, -11.4172) to (6.1786, -9.7208)
  arc A56 centre (6.2457, -9.8075) radius 0.1097 clockwise from (6.1786, -9.7208) to (6.3203, -9.7271)
  arc A57 centre (-39.755, -59.3372) radius 67.706 clockwise from (6.3203, -9.7271) to (7.2537, -10.6107)
  arc A58 centre (-4.4067, -0.8601) radius 15.2 clockwise from (5.3401, -12.5237) to (2.9927, -14.1374)
  arc A59 centre (-4.4067, -0.8601) radius 15.2 clockwise from (8.873, -8.2553) to (7.2537, -10.6107)
  arc A60 centre (-5.0124, -21.2003) radius 15.3116 clockwise from (-16.0692, -10.6082) to (-15.1488, -9.7243)
  arc A61 centre (-15.0489, -9.8031) radius 0.1272 clockwise from (-15.1488, -9.7243) to (-14.9454, -9.7291)
  arc A62 centre (-46.5076, -42.5964) radius 45.5679 clockwise from (-14.9454, -9.7291) to (-13.2817, -11.4119)
  arc A63 centre (-13.4029, -11.5164) radius 0.16 clockwise from (-13.2817, -11.4119) to (-13.2578, -11.584)
  arc A64 centre (-20.4506, -5.5922) radius 9.3615 clockwise from (-13.2578, -11.584) to (-14.1561, -12.5216)
  arc A65 centre (-4.4067, -0.8601) radius 15.2 clockwise from (-16.0692, -10.6082) to (-17.6759, -8.2743)
  arc A66 centre (-4.4067, -0.8601) radius 15.2 clockwise from (-11.8062, -14.1374) to (-14.1561, -12.5216)
  arc A67 centre (-10.4863, 10.3064) radius 0.4294 clockwise from (-10.7174, 10.6683) to (-10.1272, 10.5419)
  arc A68 centre (26.1036, 34.3038) radius 43.3278 clockwise from (-8.6611, 8.4443) to (-10.1272, 10.5419)
  arc A69 centre (-9.0012, 8.1914) radius 0.4238 clockwise from (-8.6611, 8.4443) to (-8.595, 8.0705)
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  point P2 (-4.4067, -0.8601)
  point P3 (-4.4067, -0.8601)
  point P5 (-4.4067, -0.8601)
  point P7 (-4.4067, -0.8601)
  point P9 (-4.4067, -0.8601)
  point P11 (-4.4067, 12.6425)
  point P14 (-4.4067, -14.3661)
  point P16 (-2.4989, -15.7383)
  point P19 (2.5631, 12.4223)
  point P21 (8.873, 6.5351)
  point P22 (8.873, 6.1148)
  point P23 (8.873, -7.835)
  point P24 (8.873, -8.2553)
  point P25 (2.9927, -14.1374)
  point P27 (-11.3861, -14.1374)
  point P28 (-11.8062, -14.1374)
  point P29 (-17.6759, -7.8551)
  point P30 (-17.6759, -8.2743)
  point P32 (-17.6759, 6.1349)
  point P46 (-10.4097, -0.8601)
  point P62 (-5.3601, -0.8601)
  point P63 (3.4058, -0.8601)
  point P64 (2.8964, -0.3096)
  point P68 (3.9018, -0.2975)
  point P71 (8.6743, 0.6405)
  point P80 (8.5331, 1.6276)
  point P82 (2.9074, -1.4205)
  point P93 (8.5209, -3.3585)
  point P116 (3.9081, -1.417)
  point P119 (8.671, -2.3738)
  point P145 (-16.0708, 8.8862)
  point P154 (5.3368, 10.8063)
  point P175 (7.2537, -10.6107)
  point P187 (-14.1561, -12.5216)
  coincident P2 P3
  vertical L1
  coincident P2 P5
  parallel L1 L2
  coincident P2 P7
  perpendicular L1 L3
  coincident P2 P9
  perpendicular L2 L4
  coincident L1 P11
  coincident L2 P14
  coincident P16 A3
  concentric A3 A6
  concentric A6 A44
  coincident P19 A6
  horizontal L5
  coincident P21 A44
  coincident P22 A6
  vertical L6
  coincident P23 A6
  coincident P24 A44
  parallel L6 L7
  coincident P25 A44
  perpendicular L6 L8
  coincident P27 A3
  coincident P28 A44
  parallel L8 L9
  coincident P29 A3
  coincident P30 A44
  perpendicular L9 L10
  coincident P32 A3
  perpendicular L9 L11
  perpendicular L11 L12
  concentric A3 A4
  concentric A44 A65
  concentric A4 A5
  concentric A58 A65
  concentric A6 A7
  concentric A51 A58
  concentric A7 A8
  concentric A1 C1
  concentric C1 C2
  concentric C1 C3
  concentric A1 C4
  coincident L4 P46
  concentric C5 C6
  concentric C6 C7
  concentric C7 C8
  concentric A2 C9
  concentric C9 C10
  concentric A2 C11
  concentric C9 C12
  coincident L4 P62
  coincident L3 P63
  coincident C22 P64
  horizontal L13
  coincident C22 P68
  horizontal L15
  coincident C17 P71
  tangent L16 A9
  tangent L13 A10
  tangent A10 A11
  tangent L14 A12
  tangent L14 A13
  tangent A13 A14
  coincident C17 P80
  coincident C22 P82
  parallel L13 L17
  tangent L17 A15
  tangent A16 A17
  tangent L18 A18
  tangent A18 A19
  coincident C18 P93
  horizontal L21
  tangent L19 A20
  tangent A20 A21
  tangent L20 A22
  tangent L21 A23
  tangent L21 A24
  tangent A24 A25
  tangent L19 A28
  coincident C22 P116
  parallel L3 L22
  coincident C18 P119
  tangent L22 A29
  tangent A30 A31
  tangent A31 A32
  tangent A33 A34
  tangent A34 A35
  tangent A35 A36
  tangent A36 A37
  tangent A37 A38
  tangent A37 A39
  tangent A39 A40
  tangent A30 A41
  coincident P145 A44
  perpendicular L24 L25
  tangent L26 A42
  tangent L25 A43
  concentric A44 A45
  coincident P154 A51
  concentric A51 A52
  tangent A54 A55
  tangent A56 A57
  coincident P175 A58
  concentric A58 A59
  coincident P187 A65
  concentric A65 A66
  tangent A67 A68
  tangent A68 A69
  horizontal L27
  dimension "d1" diameter A3 = 30
  dimension "d2" diameter A1 = 4.7
  dimension "d3" diameter A2 = 4.7
  dimension "d4" diameter A44 = 30.4
  dimension "d5" diameter C5 = 2
  dimension "d6" diameter C8 = 1
  dimension "d7" diameter C9 = 3.5
  dimension "d8" diameter C13 = 1
  dimension "d9" diameter C14 = 1
  dimension "d10" diameter C15 = 1
  dimension "d11" diameter C16 = 1
  dimension "d12" diameter C17 = 1
  dimension "d13" diameter C18 = 1
  dimension "d14" diameter C19 = 1
  dimension "d15" diameter C20 = 1
  dimension "d16" diameter C21 = 2.5
  dimension "d17" diameter C22 = 1.5
extrude "Extrude1" new body sketch "Sketch1" against normal blind 9 bodies "Body_Top"
extrude "Extrude2" cut sketch "Sketch1" against normal blind 1
extrude "Extrude3" cut sketch "Sketch1" profile of C1 C2 C3 C4 against normal blind 4.5
extrude "Extrude4" cut sketch "Sketch1" profile of C1 against normal blind 10
extrude "Extrude5" cut sketch "Sketch1" profile of C9 C10 C11 C12 against normal blind 4.5
extrude "Extrude6" cut sketch "Sketch1" profile of C12 against normal blind 10
extrude "Extrude7" add sketch "Sketch1" profile of C13 C14 C15 C16 C17 C18 C19 C20 along normal blind 0.3
extrude "Extrude8" cut sketch "Sketch1" profile of C22 against normal blind 0.3
extrude "Extrude9" cut sketch "Sketch1" profile of C21 against normal blind 1
extrude "Extrude10" add sketch "Sketch1" profile of C5 C6 C7 C8 along normal blind 2.3
extrude "Extrude11" new body sketch "Sketch1" profile of C8 along normal blind 9 bodies "Needle"
chamfer "Chamfer1" distance 0.4
canvas "Canvas2" bodies "Body_Top"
